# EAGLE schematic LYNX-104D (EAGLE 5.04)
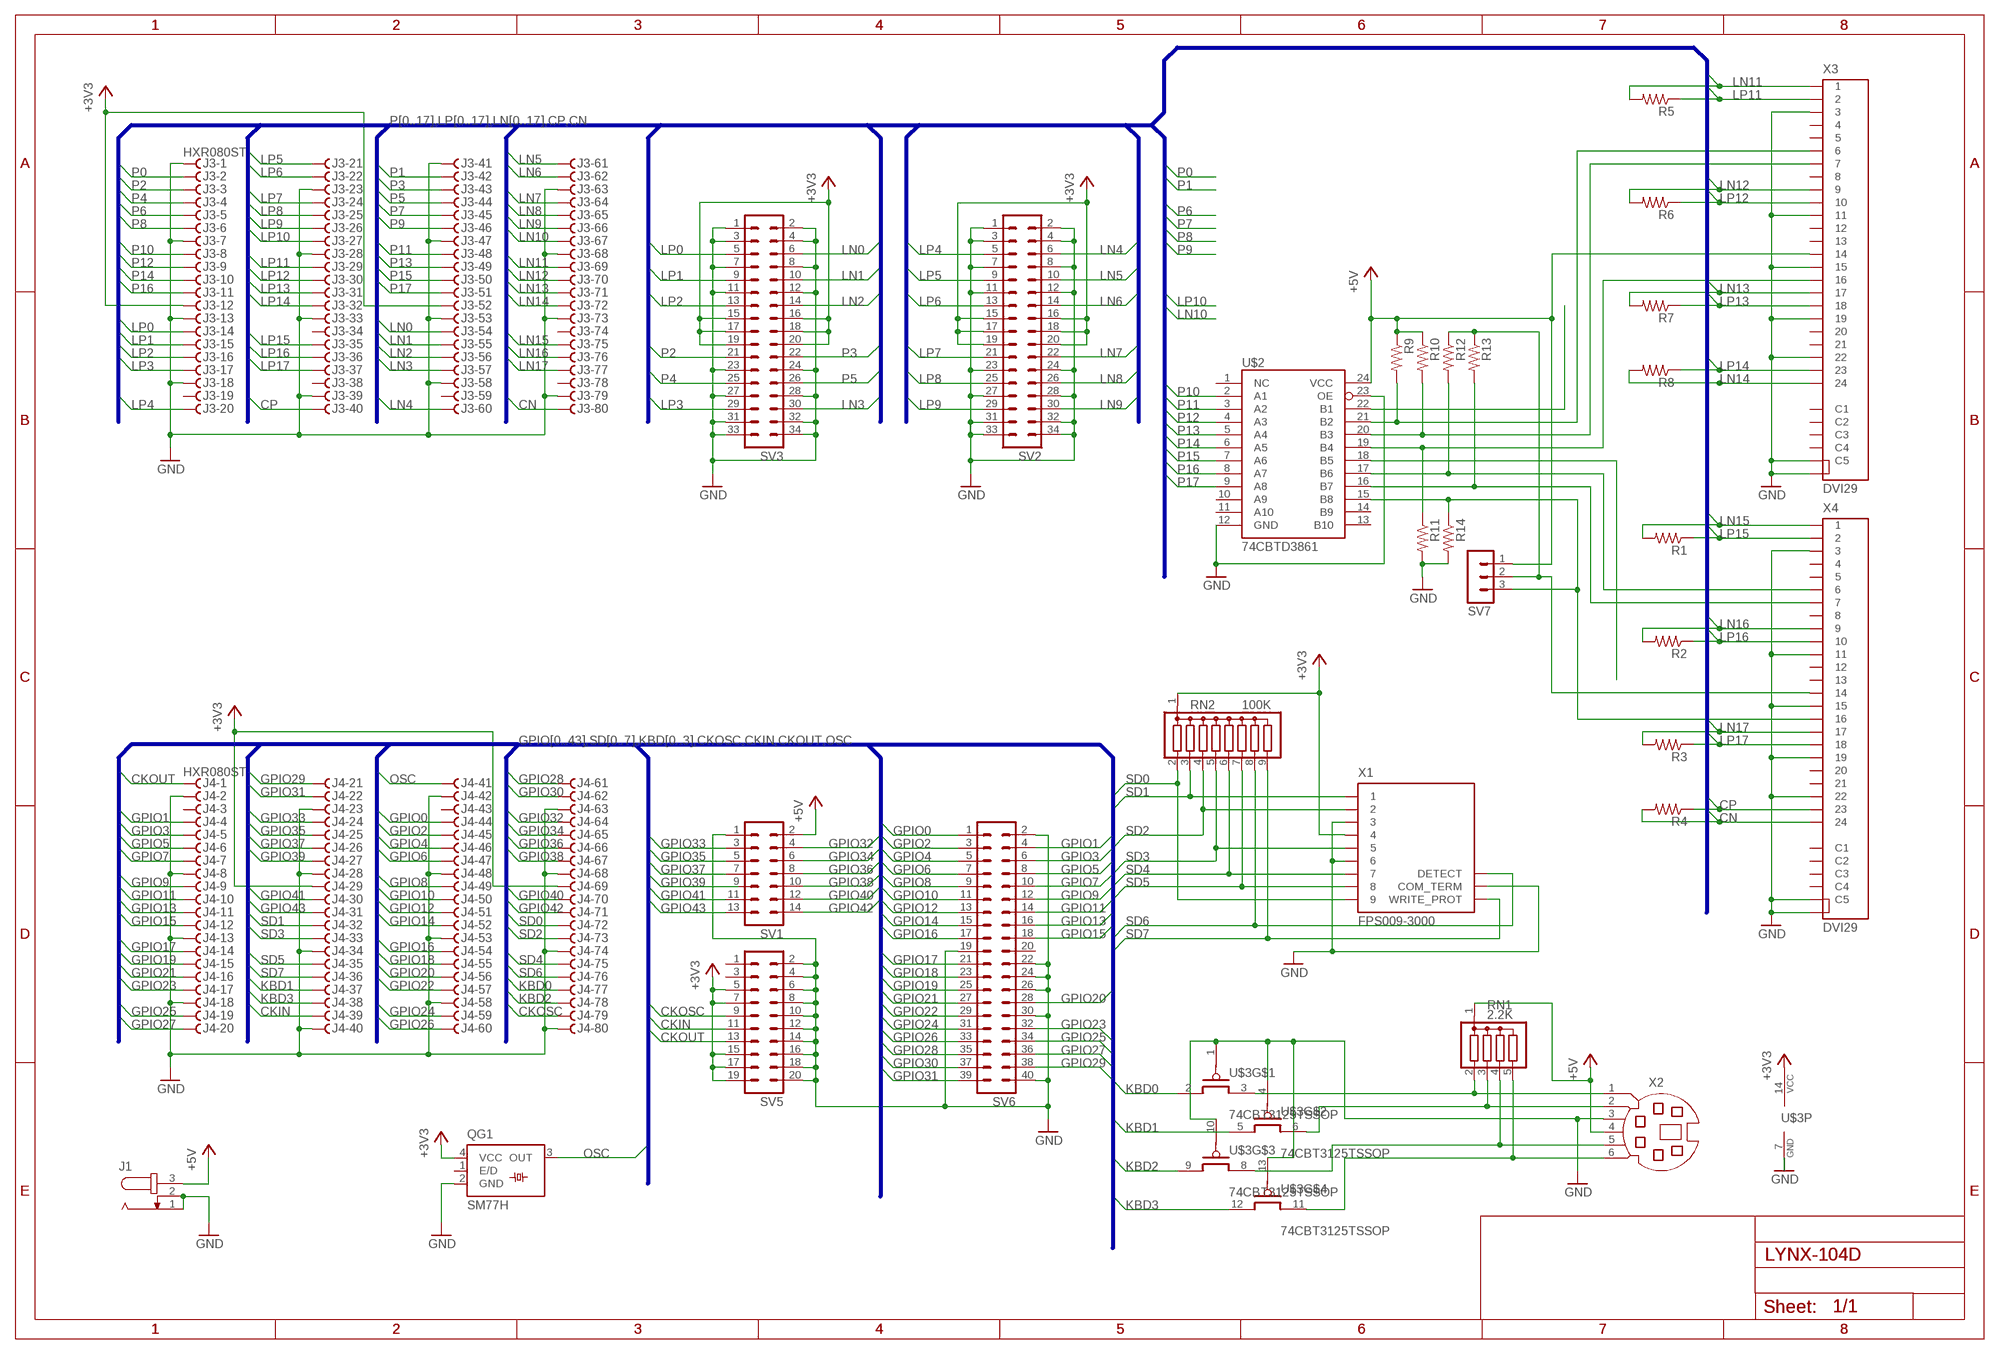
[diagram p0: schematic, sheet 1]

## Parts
J1  JACK-PLUG0  [SPC4077]
J3  HXR080ST  [HXR080ST]
J4  HXR080ST  [HXR080ST]
QG1  SM77H  [SM77H]
R1  R-US_0204/5  [0204/5]
R2  R-US_0204/5  [0204/5]
R3  R-US_0204/5  [0204/5]
R4  R-US_0204/5  [0204/5]
R5  R-US_0204/5  [0204/5]
R6  R-US_0204/5  [0204/5]
R7  R-US_0204/5  [0204/5]
R8  R-US_0204/5  [0204/5]
R9  R-US_0204/5  [0204/5]
R10  R-US_0204/5  [0204/5]
R11  R-US_0204/5  [0204/5]
R12  R-US_0204/5  [0204/5]
R13  R-US_0204/5  [0204/5]
R14  R-US_0204/5  [0204/5]
RN1  2.2K  G04R  [SIL5]
RN2  100K  G08R  [SIL9]
SV1  MA07-2  [MA07-2]
SV2  ML34  [ML34]
SV3  ML34  [ML34]
SV5  MA10-2  [MA10-2]
SV6  MA20-2  [MA20-2]
SV7  MA03-1MA03-1A  [MA03-1A]
U$2  74CBTD3861  [SO24L]
U$3  74CBT3125TSSOP  [PW_R-PDSO-G14]
X1  FPS009-3000  [FPS009-3000]
X2  MD06SS  [MDIN06SS]
X3  DVI29  [CCDVI-29DVISIR-A-2]
X4  DVI29  [CCDVI-29DVISIR-A-2]

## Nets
+3V3: J3.12 J3.52 J4.29 J4.69 QG1.4(VCC) RN2.1 SV2.15 SV2.16 SV2.17 SV2.18 SV2.19 SV2.20 SV3.15 SV3.16 SV3.17 SV3.18 SV3.19 SV3.20 SV5.5 SV5.7 SV5.15 SV5.17 SV5.19 U$3.14(P:VCC) X1.4
+5V: J1.3 R9.1 R10.1 RN1.1 SV1.2 SV7.1 U$2.24(VCC) X2.4 X3.14
CKIN: J4.39 SV5.11
CKOSC: J4.79 SV5.9
CKOUT: J4.1 SV5.13
CN: J3.80 R4.2 X4.24
CP: J3.40 R4.1 X4.23
GND: J1.1 J1.2 J3.1 J3.7 J3.13 J3.18 J3.23 J3.28 J3.33 J3.39 J3.41 J3.47 J3.53 J3.58 J3.63 J3.68 J3.73 J3.79 J4.2 J4.8 J4.13 J4.18 J4.23 J4.28 J4.34 J4.40 J4.42 J4.48 J4.53 J4.58 J4.63 J4.68 J4.74 J4.80 QG1.2(GND) R11.2 R14.2 SV1.1 SV2.1 SV2.2 SV2.3 SV2.4 SV2.7 SV2.8 SV2.11 SV2.12 SV2.23 SV2.24 SV2.27 SV2.28 SV2.31 SV2.32 SV2.33 SV2.34 SV3.1 SV3.2 SV3.3 SV3.4 SV3.7 SV3.8 SV3.11 SV3.12 SV3.23 SV3.24 SV3.27 SV3.28 SV3.31 SV3.32 SV3.33 SV3.34 SV5.2 SV5.4 SV5.6 SV5.8 SV5.10 SV5.12 SV5.14 SV5.16 SV5.18 SV5.20 SV6.2 SV6.19 SV6.22 SV6.24 SV6.26 SV6.30 SV6.40 U$2.12(GND) U$2.23(OE) U$3.1(OE) U$3.4(OE) U$3.7(P:GND) U$3.10(OE) U$3.13(OE) X1.3 X1.6 X1.COM_TERM X2.3 X3.3 X3.11 X3.15 X3.19 X3.22 X3.C5.1(C5) X3.C5.2 X4.3 X4.11 X4.15 X4.19 X4.22 X4.C5.1(C5) X4.C5.2
GPIO0: J4.44 SV6.1
GPIO1: J4.4 SV6.4
GPIO2: J4.45 SV6.3
GPIO3: J4.5 SV6.6
GPIO4: J4.46 SV6.5
GPIO5: J4.6 SV6.8
GPIO6: J4.47 SV6.7
GPIO7: J4.7 SV6.10
GPIO8: J4.49 SV6.9
GPIO9: J4.9 SV6.12
GPIO10: J4.50 SV6.11
GPIO11: J4.10 SV6.14
GPIO12: J4.51 SV6.13
GPIO13: J4.11 SV6.16
GPIO14: J4.52 SV6.15
GPIO15: J4.12 SV6.18
GPIO16: J4.54 SV6.17
GPIO17: J4.14 SV6.21
GPIO18: J4.55 SV6.23
GPIO19: J4.15 SV6.25
GPIO20: J4.56 SV6.28
GPIO21: J4.16 SV6.27
GPIO22: J4.57 SV6.29
GPIO23: J4.17 SV6.32
GPIO24: J4.59 SV6.31
GPIO25: J4.19 SV6.34
GPIO26: J4.60 SV6.33
GPIO27: J4.20 SV6.36
GPIO28: J4.61 SV6.35
GPIO29: J4.21 SV6.38
GPIO30: J4.62 SV6.37
GPIO31: J4.22 SV6.39
GPIO32: J4.64 SV1.4
GPIO33: J4.24 SV1.3
GPIO34: J4.65 SV1.6
GPIO35: J4.25 SV1.5
GPIO36: J4.66 SV1.8
GPIO37: J4.26 SV1.7
GPIO38: J4.67 SV1.10
GPIO39: J4.27 SV1.9
GPIO40: J4.70 SV1.12
GPIO41: J4.30 SV1.11
GPIO42: J4.71 SV1.14
GPIO43: J4.31 SV1.13
KBD0: J4.77 U$3.2(I)
KBD1: J4.37 U$3.5(I)
KBD2: J4.78 U$3.9(I)
KBD3: J4.38 U$3.12(I)
LN0: J3.54 SV3.6
LN1: J3.55 SV3.10
LN2: J3.56 SV3.14
LN3: J3.57 SV3.30
LN4: J3.60 SV2.6
LN5: J3.61 SV2.10
LN6: J3.62 SV2.14
LN7: J3.64 SV2.22
LN8: J3.65 SV2.26
LN9: J3.66 SV2.30
LN10: J3.67
LN11: J3.69 R5.2 X3.1
LN12: J3.70 R6.2 X3.9
LN13: J3.71 R7.2 X3.17
LN14: J3.72 R8.2 X3.24
LN15: J3.75 R1.2 X4.1
LN16: J3.76 R2.2 X4.9
LN17: J3.77 R3.2 X4.17
LP0: J3.14 SV3.5
LP1: J3.15 SV3.9
LP2: J3.16 SV3.13
LP3: J3.17 SV3.29
LP4: J3.20 SV2.5
LP5: J3.21 SV2.9
LP6: J3.22 SV2.13
LP7: J3.24 SV2.21
LP8: J3.25 SV2.25
LP9: J3.26 SV2.29
LP10: J3.27
LP11: J3.29 R5.1 X3.2
LP12: J3.30 R6.1 X3.10
LP13: J3.31 R7.1 X3.18
LP14: J3.32 R8.1 X3.23
LP15: J3.35 R1.1 X4.2
LP16: J3.36 R2.1 X4.10
LP17: J3.37 R3.1 X4.18
N$1: RN1.2 U$3.3(O) X2.1
N$2: RN1.3 U$3.6(O) X2.2
N$3: RN1.4 U$3.8(O) X2.5
N$4: RN1.5 U$3.11(O) X2.6
N$5: U$2.22(B1)
N$6: R9.2 U$2.21(B2) X3.6
N$7: R10.2 U$2.20(B3) X3.7
N$8: R11.1 U$2.19(B4) X3.16
N$9: U$2.18(B5)
N$10: R12.2 U$2.17(B6) X4.6
N$11: R13.2 U$2.16(B7) X4.7
N$12: R14.1 SV7.3 U$2.15(B8) X4.16
N$17: R12.1 R13.1 SV7.2 X4.14
OSC: J4.41 QG1.3(OUT)
P0: J3.2
P1: J3.42
P2: J3.3 SV3.21
P3: J3.43 SV3.22
P4: J3.4 SV3.25
P5: J3.44 SV3.26
P6: J3.5
P7: J3.45
P8: J3.6
P9: J3.46
P10: J3.8 U$2.2(A1)
P11: J3.48 U$2.3(A2)
P12: J3.9 U$2.4(A3)
P13: J3.49 U$2.5(A4)
P14: J3.10 U$2.6(A5)
P15: J3.50 U$2.7(A6)
P16: J3.11 U$2.8(A7)
P17: J3.51 U$2.9(A8)
SD0: J4.72 RN2.2 X1.9
SD1: J4.32 RN2.3 X1.1
SD2: J4.73 RN2.4 X1.2
SD3: J4.33 RN2.5 X1.5
SD4: J4.75 RN2.6 X1.7
SD5: J4.35 RN2.7 X1.8
SD6: J4.76 RN2.8 X1.DETECT
SD7: J4.36 RN2.9 X1.WRITE_PROT
Unconnected: J3.19 J3.34 J3.38 J3.59 J3.74 J3.78 J4.3 J4.43 QG1.1(E/D) SV5.1 SV5.3 SV6.20 U$2.1(NC) U$2.10(A9) U$2.11(A10) U$2.13(B10) U$2.14(B9) X3.4 X3.5 X3.8 X3.12 X3.13 X3.20 X3.21 X3.C1 X3.C2 X3.C3 X3.C4 X4.4 X4.5 X4.8 X4.12 X4.13 X4.20 X4.21 X4.C1 X4.C2 X4.C3 X4.C4

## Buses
GPIO[0..43],SD[0..7],KBD[0..3],CKOSC,CKIN,CKOUT,OSC
P[0..17],LP[0..17],LN[0..17],CP,CN

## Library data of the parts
J1 = sheet1:JACK-PLUG: DC POWER JACK Power Jack, DC, Right Angle, Through Hole, Rated 5A at 16VDC, PC Terminals Distributor: Farnell (www.Farnell.de) Drawing: 84N1161.pdf / 84N1162.pdf Manufacturer: SPC Technology (www.spctechnology.com) Type: SPC4077 / SPC 4078
J3 J4 = sheet1:HXR080ST: THOMAS&BETTS
QG1 = sheet1:SM77H: 3.3V CMOS Clock Oscillator Source: www.pletronics.com .. sm77h%203.3v.pdf
R1-R14 = sheet1:R-US_: RESISTOR, American symbol
RN1 = sheet1:G04R: SIL RESISTOR
RN2 = sheet1:G08R: SIL RESISTOR
SV1 = sheet1:MA07-2: PIN HEADER
SV2 SV3 = sheet1:ML34: HARTING
SV5 = sheet1:MA10-2: PIN HEADER
SV6 = sheet1:MA20-2: PIN HEADER
SV7 = sheet1:MA03-1: PIN HEADER
U$2 = sheet1:74CBTD3861
U$3 = sheet1:74CBT3125
X1 = sheet1:FPS009-300*: SD Card and MMC Reader (Manual Insertion) Source: http://www.yamaichi.de/pdf/c_fps009_3000.pdf
X2 = sheet1:MD06SS: YAMAICHI CONNECTOR
X3 X4 = sheet1:DVI29: DVI 29 Connctor Source: http://www.cypressindustries.com/pdf/CCDVI-29DVISIR-A-2.pdf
